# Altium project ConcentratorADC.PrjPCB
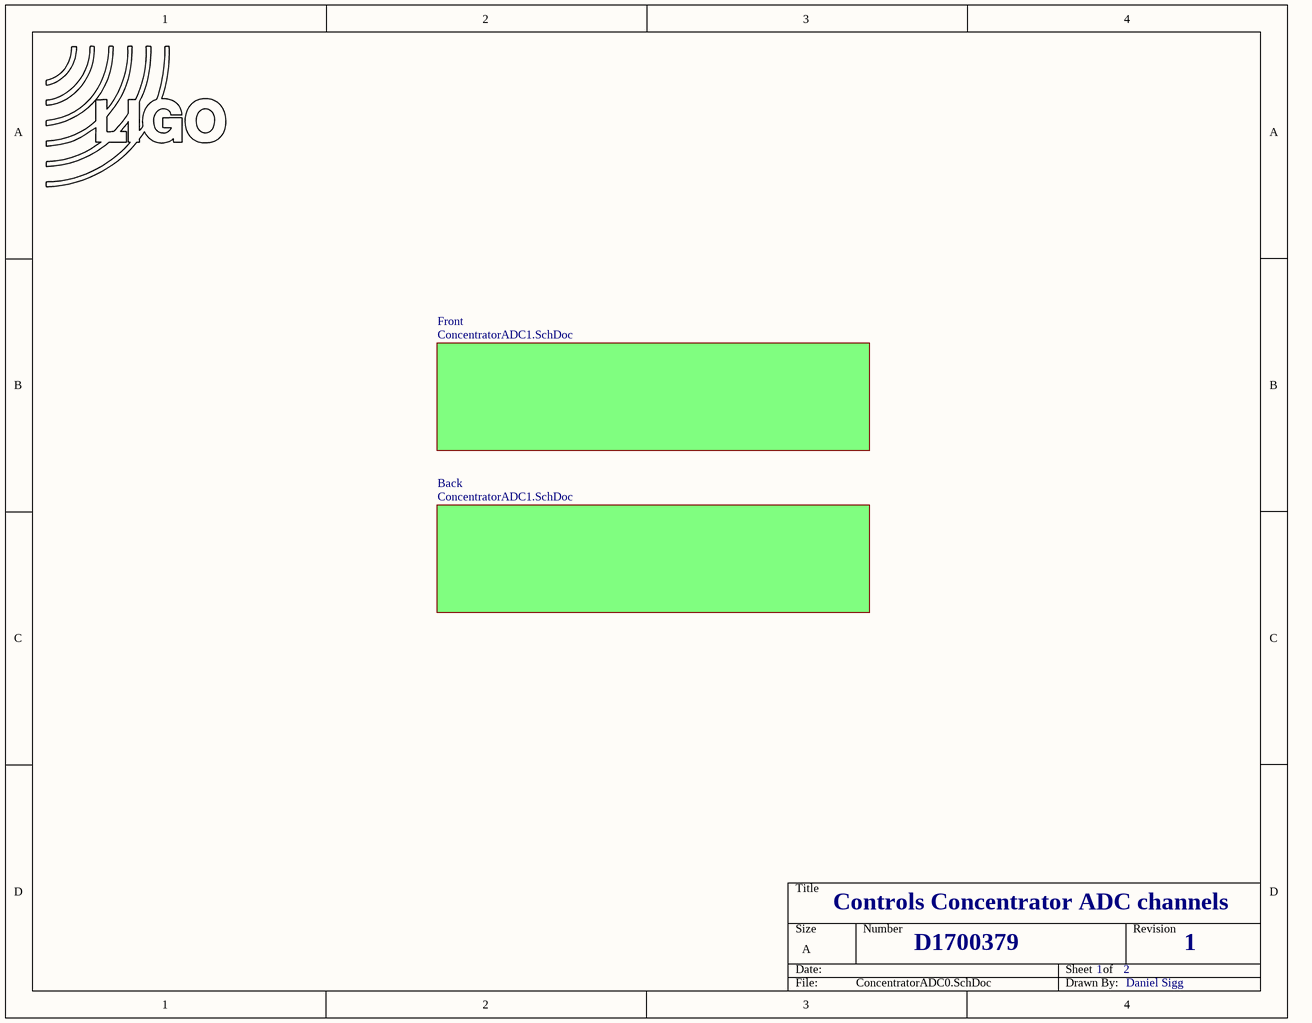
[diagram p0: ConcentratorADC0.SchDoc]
3 sheets, 115 parts. Net scope: flat (ports and power ports of the same name join across sheets).
Board file: ConcentratorADC.PcbDoc
Sheets:
  ConcentratorADC0.SchDoc
    Front = ConcentratorADC1.SchDoc
      OUT1 = ConcentratorADC2.SchDoc
      OUT2 = ConcentratorADC2.SchDoc
      OUT3 = ConcentratorADC2.SchDoc
      OUT4 = ConcentratorADC2.SchDoc
    Back = ConcentratorADC1.SchDoc
      OUT1 = ConcentratorADC2.SchDoc
      OUT2 = ConcentratorADC2.SchDoc
      OUT3 = ConcentratorADC2.SchDoc
      OUT4 = ConcentratorADC2.SchDoc

## Sheet ConcentratorADC0.SchDoc: D1700379
size A; Engineer: Daniel Sigg; Revision: 1; PageSetup: Record=PageOptions¦CenterHorizontal=True¦CenterVertical=True¦PrintScale=1.12¦XCorrection=1.00¦YCorrection=1.00¦PrintKind=0¦BorderSize=5000000¦LeftOffset=0¦BottomOffset=0¦Orientation=2¦PaperLength=1000¦PaperWidth=1000¦Scale=100¦PaperSource=7¦PrintQuality=-4¦MediaType=1¦DitherType=10¦PaperKind=Letter¦PrintScaleMode=1

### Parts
LOGO1  LIGO logo  [LIGO_LOGO]  (value not drawn)  (no BOM)

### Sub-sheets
Back = ConcentratorADC1.SchDoc: no entries
Front = ConcentratorADC1.SchDoc: no entries

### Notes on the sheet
- Controls Concentrator ADC channels
- D1700379
- 1
- 2
- Daniel Sigg

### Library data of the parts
LOGO1 = LIGO_logo

## Sheet ConcentratorADC1.SchDoc: D1700379
size A; Engineer: Daniel Sigg; Revision: 1; PageSetup: Record=PageOptions¦CenterHorizontal=True¦CenterVertical=True¦PrintScale=1.12¦XCorrection=1.00¦YCorrection=1.00¦PrintKind=0¦BorderSize=5000000¦LeftOffset=0¦BottomOffset=0¦Orientation=2¦PaperLength=1000¦PaperWidth=1000¦Scale=100¦PaperSource=7¦PrintQuality=-4¦MediaType=1¦DitherType=10¦PaperKind=Letter¦PrintScaleMode=1
Used 2 times, as channels Front, Back. Parts and nets are listed once, with the designators drawn on the sheet.
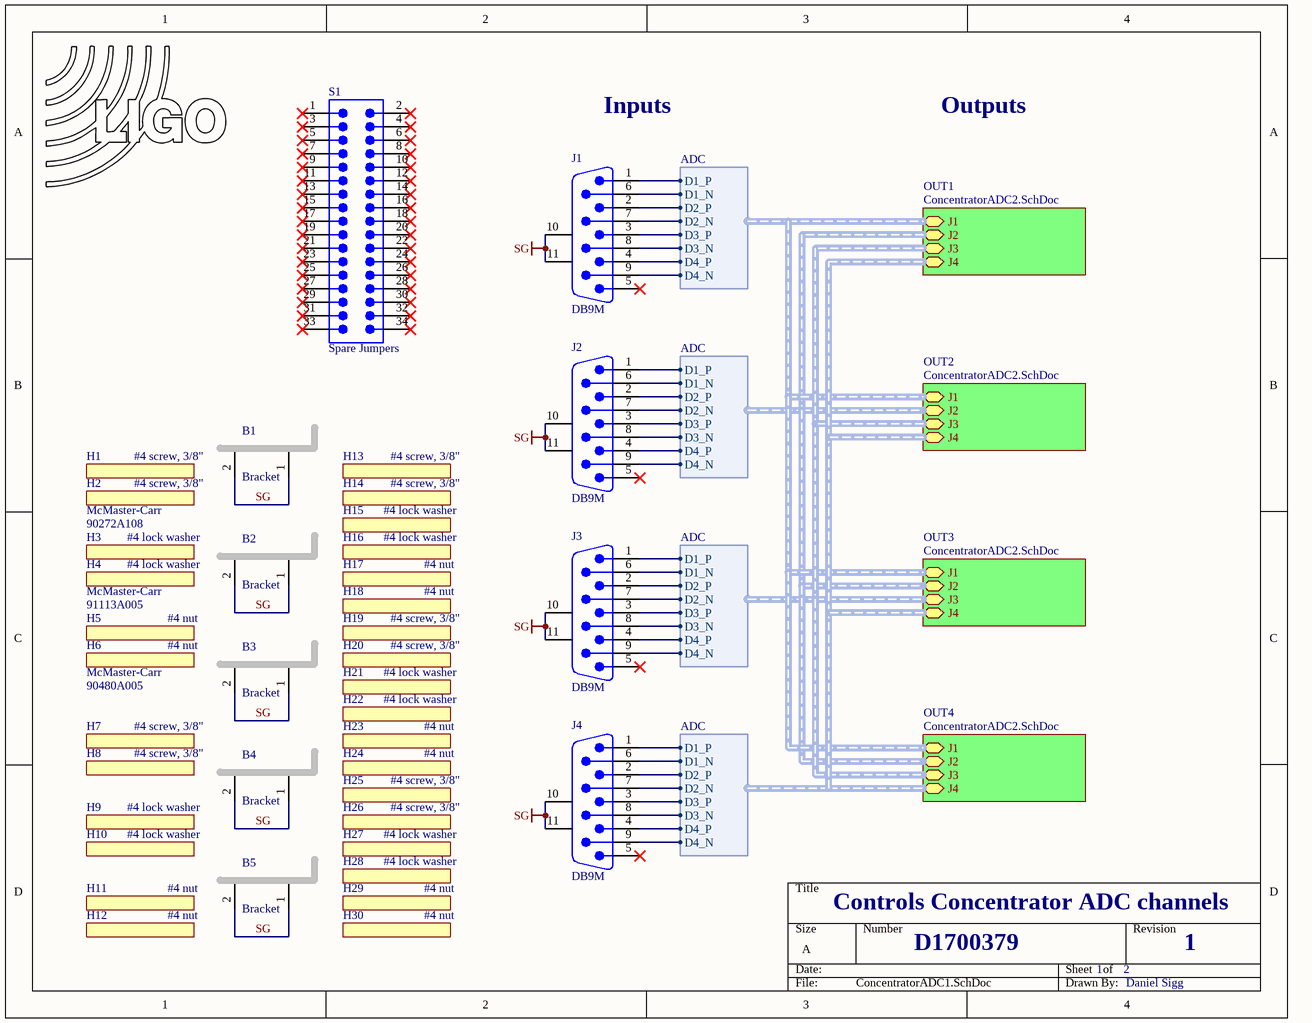
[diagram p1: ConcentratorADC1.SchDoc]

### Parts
B1  Bracket  [Bracket-RA_708]
B2  Bracket  [Bracket-RA_708]
B3  Bracket  [Bracket-RA_708]
B4  Bracket  [Bracket-RA_708]
B5  Bracket  [Bracket-RA_708]
H1  #4 screw, 3/8"  (mechanical)
H2  #4 screw, 3/8"  Part Number: 90272A108  Distributor: McMaster-Carr  (mechanical)
H3  #4 lock washer  (mechanical)
H4  #4 lock washer  Part Number: 91113A005  Distributor: McMaster-Carr  (mechanical)
H5  #4 nut  (mechanical)
H6  #4 nut  Part Number: 90480A005  Distributor: McMaster-Carr  (mechanical)
H7  #4 screw, 3/8"  (mechanical)
H8  #4 screw, 3/8"  (mechanical)
H9  #4 lock washer  (mechanical)
H10  #4 lock washer  (mechanical)
H11  #4 nut  (mechanical)
H12  #4 nut  (mechanical)
H13  #4 screw, 3/8"  (mechanical)
H14  #4 screw, 3/8"  (mechanical)
H15  #4 lock washer  (mechanical)
H16  #4 lock washer  (mechanical)
H17  #4 nut  (mechanical)
H18  #4 nut  (mechanical)
H19  #4 screw, 3/8"  (mechanical)
H20  #4 screw, 3/8"  (mechanical)
H21  #4 lock washer  (mechanical)
H22  #4 lock washer  (mechanical)
H23  #4 nut  (mechanical)
H24  #4 nut  (mechanical)
H25  #4 screw, 3/8"  (mechanical)
H26  #4 screw, 3/8"  (mechanical)
H27  #4 lock washer  (mechanical)
H28  #4 lock washer  (mechanical)
H29  #4 nut  (mechanical)
H30  #4 nut  (mechanical)
J1  DB9M  [DB9M-RA]
J2  DB9M  [DB9M-RA]
J3  DB9M  [DB9M-RA]
J4  DB9M  [DB9M-RA]
LOGO1  LIGO logo  [LIGO_LOGO]  (value not drawn)  (graphical)
S1  Spare Jumpers  [9181349421]

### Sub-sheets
OUT1 = ConcentratorADC2.SchDoc: J1 (harness ADC), J2 (harness ADC), J3 (harness ADC), J4 (harness ADC)
OUT2 = ConcentratorADC2.SchDoc: J1 (harness ADC), J2 (harness ADC), J3 (harness ADC), J4 (harness ADC)
OUT3 = ConcentratorADC2.SchDoc: J1 (harness ADC), J2 (harness ADC), J3 (harness ADC), J4 (harness ADC)
OUT4 = ConcentratorADC2.SchDoc: J1 (harness ADC), J2 (harness ADC), J3 (harness ADC), J4 (harness ADC)

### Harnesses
ADC: D1_P, D1_N, D2_P, D2_N, D3_P, D3_N, D4_P, D4_N

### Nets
SG: B1.1(GND) B1.2(GND) B2.1(GND) B2.2(GND) B3.1(GND) B3.2(GND) B4.1(GND) B4.2(GND) B5.1(GND) B5.2(GND) J1.10(MH1) J1.11(MH2) J2.10(MH1) J2.11(MH2) J3.10(MH1) J3.11(MH2) J4.10(MH1) J4.11(MH2)
NetJ1_1: J1.1 ; sheet OUT1/J1.D1_P
NetJ1_2: J1.2 ; sheet OUT1/J1.D2_P
NetJ1_3: J1.3 ; sheet OUT1/J1.D3_P
NetJ1_4: J1.4 ; sheet OUT1/J1.D4_P
NetJ1_6: J1.6 ; sheet OUT1/J1.D1_N
NetJ1_7: J1.7 ; sheet OUT1/J1.D2_N
NetJ1_8: J1.8 ; sheet OUT1/J1.D3_N
NetJ1_9: J1.9 ; sheet OUT1/J1.D4_N
NetJ2_1: J2.1 ; sheet OUT1/J2.D1_P
NetJ2_2: J2.2 ; sheet OUT1/J2.D2_P
NetJ2_3: J2.3 ; sheet OUT1/J2.D3_P
NetJ2_4: J2.4 ; sheet OUT1/J2.D4_P
NetJ2_6: J2.6 ; sheet OUT1/J2.D1_N
NetJ2_7: J2.7 ; sheet OUT1/J2.D2_N
NetJ2_8: J2.8 ; sheet OUT1/J2.D3_N
NetJ2_9: J2.9 ; sheet OUT1/J2.D4_N
NetJ3_1: J3.1 ; sheet OUT1/J3.D1_P
NetJ3_2: J3.2 ; sheet OUT1/J3.D2_P
NetJ3_3: J3.3 ; sheet OUT1/J3.D3_P
NetJ3_4: J3.4 ; sheet OUT1/J3.D4_P
NetJ3_6: J3.6 ; sheet OUT1/J3.D1_N
NetJ3_7: J3.7 ; sheet OUT1/J3.D2_N
NetJ3_8: J3.8 ; sheet OUT1/J3.D3_N
NetJ3_9: J3.9 ; sheet OUT1/J3.D4_N
NetJ4_1: J4.1 ; sheet OUT1/J4.D1_P
NetJ4_2: J4.2 ; sheet OUT1/J4.D2_P
NetJ4_3: J4.3 ; sheet OUT1/J4.D3_P
NetJ4_4: J4.4 ; sheet OUT1/J4.D4_P
NetJ4_6: J4.6 ; sheet OUT1/J4.D1_N
NetJ4_7: J4.7 ; sheet OUT1/J4.D2_N
NetJ4_8: J4.8 ; sheet OUT1/J4.D3_N
NetJ4_9: J4.9 ; sheet OUT1/J4.D4_N

Not connected (* = marked no-connect by the designer): J1 5*; J2 5*; J3 5*; J4 5*; S1 1* 2* 3* 4* 5* 6* 7* 8* 9* 10* 11* 12* 13* 14* 15* 16* 17* 18* 19* 20* 21* 22* 23* 24* 25* 26* 27* 28* 29* 30* 31* 32* 33* 34*

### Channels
Front: designators B1=B1B B2=B2B B3=B3B B4=B4B B5=B5B H1=H1A H2=H2A H3=H3A H4=H4A H5=H5A H6=H6A H7=H7A H8=H8A H9=H9A H10=H10A H11=H11A H12=H12A H13=H13A H14=H14A H15=H15A H16=H16A H17=H17A H18=H18A H19=H19A H20=H20A H21=H21A H22=H22A H23=H23A H24=H24A H25=H25A H26=H26A H27=H27A H28=H28A H29=H29A H30=H30A J1=J1B J2=J2B J3=J3B J4=J4B LOGO1=LOGO1A S1=S1B
Back: designators B1=B1A B2=B2A B3=B3A B4=B4A B5=B5A H1=H1B H2=H2B H3=H3B H4=H4B H5=H5B H6=H6B H7=H7B H8=H8B H9=H9B H10=H10B H11=H11B H12=H12B H13=H13B H14=H14B H15=H15B H16=H16B H17=H17B H18=H18B H19=H19B H20=H20B H21=H21B H22=H22B H23=H23B H24=H24B H25=H25B H26=H26B H27=H27B H28=H28B H29=H29B H30=H30B J1=J1A J2=J2A J3=J3A J4=J4A LOGO1=LOGO1B S1=S1A

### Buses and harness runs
harness sheet OUT1/J1 = sheet OUT2/J1 = sheet OUT3/J1 = sheet OUT4/J1
harness sheet OUT1/J2 = sheet OUT2/J2 = sheet OUT3/J2 = sheet OUT4/J2
harness sheet OUT1/J3 = sheet OUT2/J3 = sheet OUT3/J3 = sheet OUT4/J3
harness sheet OUT1/J4 = sheet OUT2/J4 = sheet OUT3/J4 = sheet OUT4/J4

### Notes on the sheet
- Inputs
- Outputs
- Controls Concentrator ADC channels
- D1700379
- 1
- 2
- Daniel Sigg

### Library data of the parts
B1-B5 = Bracket_708: Keystone Electronics right-angle 6-32 steel, 708; Part Number: 708K-ND
H1 H7 H8 H13 H14 H19 H20 H25 H26 = Partlist: Mounting hardware; Part Number: 90272A108
H2 H4 H6 = Partlist: Mounting hardware
H3 H9 H10 H15 H16 H21 H22 H27 H28 = Partlist: Mounting hardware; Part Number: 91113A005
H5 H11 H12 H17 H18 H23 H24 H29 H30 = Partlist: Mounting hardware; Part Number: 90480A005
J1-J4 = DB9M: Plug Assembly, 9 Position, Right Angle, .318 Series; Part Number: A32094-ND
LOGO1 = LIGO_logo
S1 = 09 18 134 9421: Flat Cable Connector (IDC), PCB Transition Connector, 2 Rows, Kinked Solder Pin, 34 Contacts; Part Number: 609-3208-ND

## Sheet ConcentratorADC2.SchDoc
size A
Used 8 times, as channels Front/OUT1, Front/OUT2, Front/OUT3, Front/OUT4, Back/OUT1, Back/OUT2, Back/OUT3, Back/OUT4. Parts and nets are listed once, with the designators drawn on the sheet.
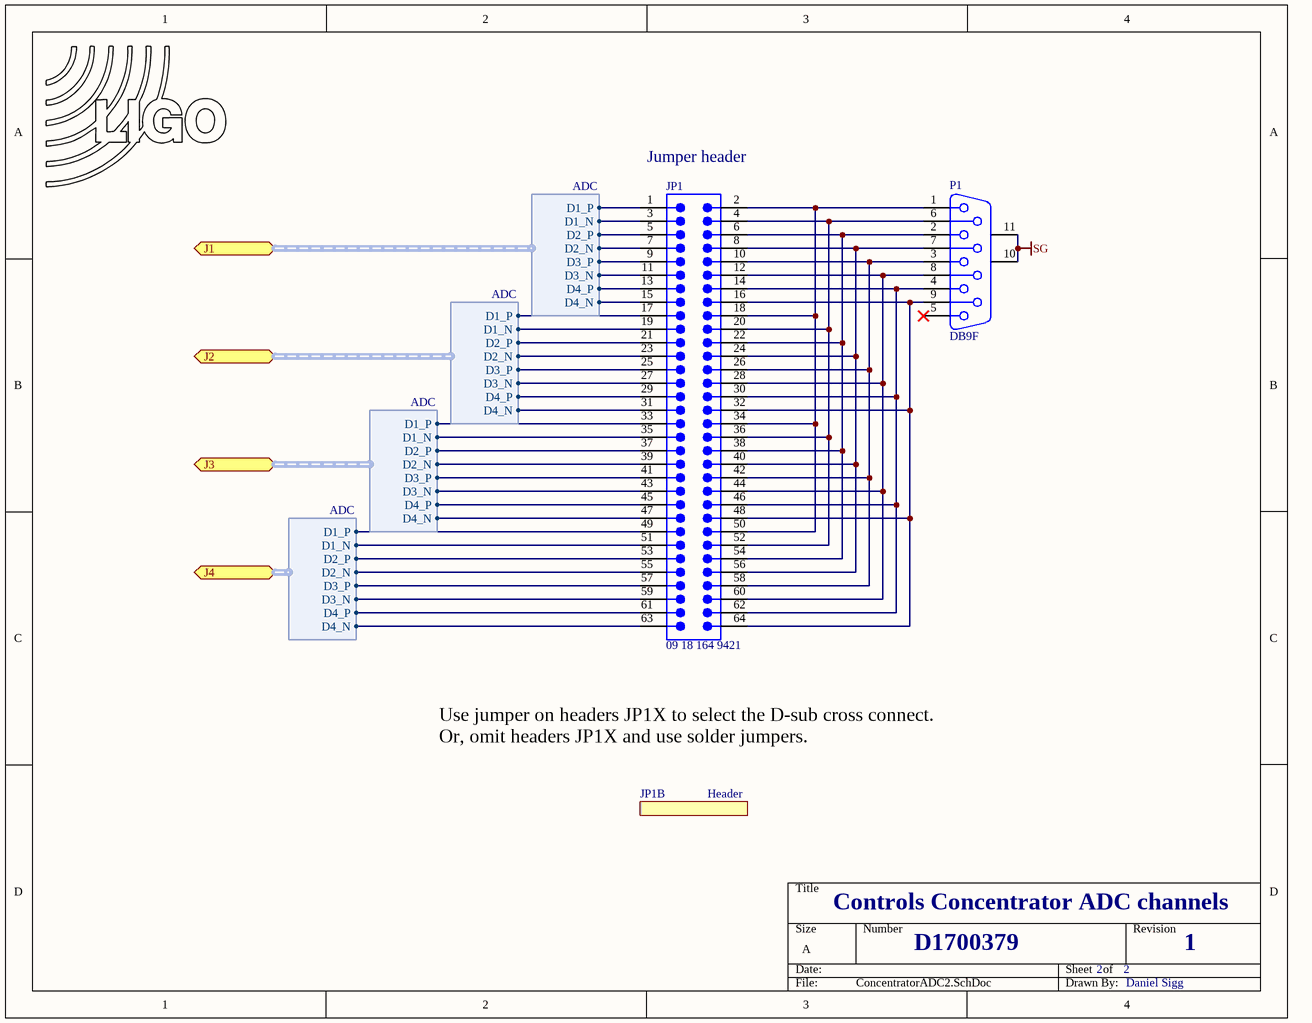
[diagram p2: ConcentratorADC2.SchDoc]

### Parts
JP1  09 18 164 9421  [9181649421]
JP1B  Header  (mechanical)
LOGO?  LIGO logo  [LIGO_LOGO]  (value not drawn)  (graphical)
P1  DB9F  [DB9F-RA]

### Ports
J1 (harness ADC), J2 (harness ADC), J3 (harness ADC), J4 (harness ADC)

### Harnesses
ADC: D1_P, D1_N, D2_P, D2_N, D3_P, D3_N, D4_P, D4_N

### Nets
SG: P1.10(MH1) P1.11(MH2)
NetJP1_1: JP1.1 ; port J1.D1_P
NetJP1_2: JP1.2 JP1.18 JP1.34 JP1.50 P1.1
NetJP1_3: JP1.3 ; port J1.D1_N
NetJP1_4: JP1.4 JP1.20 JP1.36 JP1.52 P1.6
NetJP1_5: JP1.5 ; port J1.D2_P
NetJP1_6: JP1.6 JP1.22 JP1.38 JP1.54 P1.2
NetJP1_7: JP1.7 ; port J1.D2_N
NetJP1_8: JP1.8 JP1.24 JP1.40 JP1.56 P1.7
NetJP1_9: JP1.9 ; port J1.D3_P
NetJP1_10: JP1.10 JP1.26 JP1.42 JP1.58 P1.3
NetJP1_11: JP1.11 ; port J1.D3_N
NetJP1_12: JP1.12 JP1.28 JP1.44 JP1.60 P1.8
NetJP1_13: JP1.13 ; port J1.D4_P
NetJP1_14: JP1.14 JP1.30 JP1.46 JP1.62 P1.4
NetJP1_15: JP1.15 ; port J1.D4_N
NetJP1_16: JP1.16 JP1.32 JP1.48 JP1.64 P1.9
NetJP1_17: JP1.17 ; port J2.D1_P
NetJP1_19: JP1.19 ; port J2.D1_N
NetJP1_21: JP1.21 ; port J2.D2_P
NetJP1_23: JP1.23 ; port J2.D2_N
NetJP1_25: JP1.25 ; port J2.D3_P
NetJP1_27: JP1.27 ; port J2.D3_N
NetJP1_29: JP1.29 ; port J2.D4_P
NetJP1_31: JP1.31 ; port J2.D4_N
NetJP1_33: JP1.33 ; port J3.D1_P
NetJP1_35: JP1.35 ; port J3.D1_N
NetJP1_37: JP1.37 ; port J3.D2_P
NetJP1_39: JP1.39 ; port J3.D2_N
NetJP1_41: JP1.41 ; port J3.D3_P
NetJP1_43: JP1.43 ; port J3.D3_N
NetJP1_45: JP1.45 ; port J3.D4_P
NetJP1_47: JP1.47 ; port J3.D4_N
NetJP1_49: JP1.49 ; port J4.D1_P
NetJP1_51: JP1.51 ; port J4.D1_N
NetJP1_53: JP1.53 ; port J4.D2_P
NetJP1_55: JP1.55 ; port J4.D2_N
NetJP1_57: JP1.57 ; port J4.D3_P
NetJP1_59: JP1.59 ; port J4.D3_N
NetJP1_61: JP1.61 ; port J4.D4_P
NetJP1_63: JP1.63 ; port J4.D4_N

Not connected (* = marked no-connect by the designer): P1 5*

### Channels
Front/OUT1: designators JP1=JP1E JP1B=JP1BA LOGO?=LOGO?A P1=P1E
Front/OUT2: designators JP1=JP1F JP1B=JP1BB LOGO?=LOGO?B P1=P1F
Front/OUT3: designators JP1=JP1G JP1B=JP1BC LOGO?=LOGO?C P1=P1G
Front/OUT4: designators JP1=JP1H JP1B=JP1BD LOGO?=LOGO?D P1=P1H
Back/OUT1: designators JP1=JP1A JP1B=JP1BE LOGO?=LOGO?E P1=P1A
Back/OUT2: designators JP1=JP1B JP1B=JP1BF LOGO?=LOGO?F P1=P1B
Back/OUT3: designators JP1=JP1C JP1B=JP1BG LOGO?=LOGO?G P1=P1C
Back/OUT4: designators JP1=JP1D JP1B=JP1BH LOGO?=LOGO?H P1=P1D

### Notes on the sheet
- (near JP1) Jumper header
- Use jumper on headers JP1X to select the D-sub cross connect.
  Or, omit headers JP1X and use solder jumpers.
- Controls Concentrator ADC channels
- D1700379
- 2
- 1
- Daniel Sigg

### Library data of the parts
JP1 = 09 18 164 9421: Flat Cable Connector (IDC), PCB Transition Connector, 2 Rows, Kinked Solder Pin, 64 Contacts; Part Number: 609-3208-ND
JP1B = Partlist: Mounting hardware; Part Number: 609-3208-ND
LOGO? = LIGO_logo
P1 = DB9F: Receptacle Assembly, 9 Position, Right Angle, .318 Series; Part Number: A32119-ND

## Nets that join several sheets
SG: Front (18 pins), Front/OUT1 (P1E.10 P1E.11), Front/OUT2 (P1F.10 P1F.11), Front/OUT3 (P1G.10 P1G.11), Front/OUT4 (P1H.10 P1H.11), Back (18 pins), Back/OUT1 (P1A.10 P1A.11), Back/OUT2 (P1B.10 P1B.11), Back/OUT3 (P1C.10 P1C.11), Back/OUT4 (P1D.10 P1D.11)
NetJP1A_1: Front/OUT1 (JP1E.1), Front/OUT2 (JP1F.1), Front/OUT3 (JP1G.1), Front/OUT4 (JP1H.1), Back/OUT1 (JP1A.1), Back/OUT2 (JP1B.1), Back/OUT3 (JP1C.1), Back/OUT4 (JP1D.1)
NetJP1A_3: Front/OUT1 (JP1E.3), Front/OUT2 (JP1F.3), Front/OUT3 (JP1G.3), Front/OUT4 (JP1H.3), Back/OUT1 (JP1A.3), Back/OUT2 (JP1B.3), Back/OUT3 (JP1C.3), Back/OUT4 (JP1D.3)
NetJP1A_5: Front/OUT1 (JP1E.5), Front/OUT2 (JP1F.5), Front/OUT3 (JP1G.5), Front/OUT4 (JP1H.5), Back/OUT1 (JP1A.5), Back/OUT2 (JP1B.5), Back/OUT3 (JP1C.5), Back/OUT4 (JP1D.5)
NetJP1A_7: Front/OUT1 (JP1E.7), Front/OUT2 (JP1F.7), Front/OUT3 (JP1G.7), Front/OUT4 (JP1H.7), Back/OUT1 (JP1A.7), Back/OUT2 (JP1B.7), Back/OUT3 (JP1C.7), Back/OUT4 (JP1D.7)
NetJP1A_9: Front/OUT1 (JP1E.9), Front/OUT2 (JP1F.9), Front/OUT3 (JP1G.9), Front/OUT4 (JP1H.9), Back/OUT1 (JP1A.9), Back/OUT2 (JP1B.9), Back/OUT3 (JP1C.9), Back/OUT4 (JP1D.9)
NetJP1A_11: Front/OUT1 (JP1E.11), Front/OUT2 (JP1F.11), Front/OUT3 (JP1G.11), Front/OUT4 (JP1H.11), Back/OUT1 (JP1A.11), Back/OUT2 (JP1B.11), Back/OUT3 (JP1C.11), Back/OUT4 (JP1D.11)
NetJP1A_13: Front/OUT1 (JP1E.13), Front/OUT2 (JP1F.13), Front/OUT3 (JP1G.13), Front/OUT4 (JP1H.13), Back/OUT1 (JP1A.13), Back/OUT2 (JP1B.13), Back/OUT3 (JP1C.13), Back/OUT4 (JP1D.13)
NetJP1A_15: Front/OUT1 (JP1E.15), Front/OUT2 (JP1F.15), Front/OUT3 (JP1G.15), Front/OUT4 (JP1H.15), Back/OUT1 (JP1A.15), Back/OUT2 (JP1B.15), Back/OUT3 (JP1C.15), Back/OUT4 (JP1D.15)
NetJP1A_17: Front/OUT1 (JP1E.17), Front/OUT2 (JP1F.17), Front/OUT3 (JP1G.17), Front/OUT4 (JP1H.17), Back/OUT1 (JP1A.17), Back/OUT2 (JP1B.17), Back/OUT3 (JP1C.17), Back/OUT4 (JP1D.17)
NetJP1A_19: Front/OUT1 (JP1E.19), Front/OUT2 (JP1F.19), Front/OUT3 (JP1G.19), Front/OUT4 (JP1H.19), Back/OUT1 (JP1A.19), Back/OUT2 (JP1B.19), Back/OUT3 (JP1C.19), Back/OUT4 (JP1D.19)
NetJP1A_21: Front/OUT1 (JP1E.21), Front/OUT2 (JP1F.21), Front/OUT3 (JP1G.21), Front/OUT4 (JP1H.21), Back/OUT1 (JP1A.21), Back/OUT2 (JP1B.21), Back/OUT3 (JP1C.21), Back/OUT4 (JP1D.21)
NetJP1A_23: Front/OUT1 (JP1E.23), Front/OUT2 (JP1F.23), Front/OUT3 (JP1G.23), Front/OUT4 (JP1H.23), Back/OUT1 (JP1A.23), Back/OUT2 (JP1B.23), Back/OUT3 (JP1C.23), Back/OUT4 (JP1D.23)
NetJP1A_25: Front/OUT1 (JP1E.25), Front/OUT2 (JP1F.25), Front/OUT3 (JP1G.25), Front/OUT4 (JP1H.25), Back/OUT1 (JP1A.25), Back/OUT2 (JP1B.25), Back/OUT3 (JP1C.25), Back/OUT4 (JP1D.25)
NetJP1A_27: Front/OUT1 (JP1E.27), Front/OUT2 (JP1F.27), Front/OUT3 (JP1G.27), Front/OUT4 (JP1H.27), Back/OUT1 (JP1A.27), Back/OUT2 (JP1B.27), Back/OUT3 (JP1C.27), Back/OUT4 (JP1D.27)
NetJP1A_29: Front/OUT1 (JP1E.29), Front/OUT2 (JP1F.29), Front/OUT3 (JP1G.29), Front/OUT4 (JP1H.29), Back/OUT1 (JP1A.29), Back/OUT2 (JP1B.29), Back/OUT3 (JP1C.29), Back/OUT4 (JP1D.29)
NetJP1A_31: Front/OUT1 (JP1E.31), Front/OUT2 (JP1F.31), Front/OUT3 (JP1G.31), Front/OUT4 (JP1H.31), Back/OUT1 (JP1A.31), Back/OUT2 (JP1B.31), Back/OUT3 (JP1C.31), Back/OUT4 (JP1D.31)
NetJP1A_33: Front/OUT1 (JP1E.33), Front/OUT2 (JP1F.33), Front/OUT3 (JP1G.33), Front/OUT4 (JP1H.33), Back/OUT1 (JP1A.33), Back/OUT2 (JP1B.33), Back/OUT3 (JP1C.33), Back/OUT4 (JP1D.33)
NetJP1A_35: Front/OUT1 (JP1E.35), Front/OUT2 (JP1F.35), Front/OUT3 (JP1G.35), Front/OUT4 (JP1H.35), Back/OUT1 (JP1A.35), Back/OUT2 (JP1B.35), Back/OUT3 (JP1C.35), Back/OUT4 (JP1D.35)
NetJP1A_37: Front/OUT1 (JP1E.37), Front/OUT2 (JP1F.37), Front/OUT3 (JP1G.37), Front/OUT4 (JP1H.37), Back/OUT1 (JP1A.37), Back/OUT2 (JP1B.37), Back/OUT3 (JP1C.37), Back/OUT4 (JP1D.37)
NetJP1A_39: Front/OUT1 (JP1E.39), Front/OUT2 (JP1F.39), Front/OUT3 (JP1G.39), Front/OUT4 (JP1H.39), Back/OUT1 (JP1A.39), Back/OUT2 (JP1B.39), Back/OUT3 (JP1C.39), Back/OUT4 (JP1D.39)
NetJP1A_41: Front/OUT1 (JP1E.41), Front/OUT2 (JP1F.41), Front/OUT3 (JP1G.41), Front/OUT4 (JP1H.41), Back/OUT1 (JP1A.41), Back/OUT2 (JP1B.41), Back/OUT3 (JP1C.41), Back/OUT4 (JP1D.41)
NetJP1A_43: Front/OUT1 (JP1E.43), Front/OUT2 (JP1F.43), Front/OUT3 (JP1G.43), Front/OUT4 (JP1H.43), Back/OUT1 (JP1A.43), Back/OUT2 (JP1B.43), Back/OUT3 (JP1C.43), Back/OUT4 (JP1D.43)
NetJP1A_45: Front/OUT1 (JP1E.45), Front/OUT2 (JP1F.45), Front/OUT3 (JP1G.45), Front/OUT4 (JP1H.45), Back/OUT1 (JP1A.45), Back/OUT2 (JP1B.45), Back/OUT3 (JP1C.45), Back/OUT4 (JP1D.45)
NetJP1A_47: Front/OUT1 (JP1E.47), Front/OUT2 (JP1F.47), Front/OUT3 (JP1G.47), Front/OUT4 (JP1H.47), Back/OUT1 (JP1A.47), Back/OUT2 (JP1B.47), Back/OUT3 (JP1C.47), Back/OUT4 (JP1D.47)
NetJP1A_49: Front/OUT1 (JP1E.49), Front/OUT2 (JP1F.49), Front/OUT3 (JP1G.49), Front/OUT4 (JP1H.49), Back/OUT1 (JP1A.49), Back/OUT2 (JP1B.49), Back/OUT3 (JP1C.49), Back/OUT4 (JP1D.49)
NetJP1A_51: Front/OUT1 (JP1E.51), Front/OUT2 (JP1F.51), Front/OUT3 (JP1G.51), Front/OUT4 (JP1H.51), Back/OUT1 (JP1A.51), Back/OUT2 (JP1B.51), Back/OUT3 (JP1C.51), Back/OUT4 (JP1D.51)
NetJP1A_53: Front/OUT1 (JP1E.53), Front/OUT2 (JP1F.53), Front/OUT3 (JP1G.53), Front/OUT4 (JP1H.53), Back/OUT1 (JP1A.53), Back/OUT2 (JP1B.53), Back/OUT3 (JP1C.53), Back/OUT4 (JP1D.53)
NetJP1A_55: Front/OUT1 (JP1E.55), Front/OUT2 (JP1F.55), Front/OUT3 (JP1G.55), Front/OUT4 (JP1H.55), Back/OUT1 (JP1A.55), Back/OUT2 (JP1B.55), Back/OUT3 (JP1C.55), Back/OUT4 (JP1D.55)
NetJP1A_57: Front/OUT1 (JP1E.57), Front/OUT2 (JP1F.57), Front/OUT3 (JP1G.57), Front/OUT4 (JP1H.57), Back/OUT1 (JP1A.57), Back/OUT2 (JP1B.57), Back/OUT3 (JP1C.57), Back/OUT4 (JP1D.57)
NetJP1A_59: Front/OUT1 (JP1E.59), Front/OUT2 (JP1F.59), Front/OUT3 (JP1G.59), Front/OUT4 (JP1H.59), Back/OUT1 (JP1A.59), Back/OUT2 (JP1B.59), Back/OUT3 (JP1C.59), Back/OUT4 (JP1D.59)
NetJP1A_61: Front/OUT1 (JP1E.61), Front/OUT2 (JP1F.61), Front/OUT3 (JP1G.61), Front/OUT4 (JP1H.61), Back/OUT1 (JP1A.61), Back/OUT2 (JP1B.61), Back/OUT3 (JP1C.61), Back/OUT4 (JP1D.61)
NetJP1A_63: Front/OUT1 (JP1E.63), Front/OUT2 (JP1F.63), Front/OUT3 (JP1G.63), Front/OUT4 (JP1H.63), Back/OUT1 (JP1A.63), Back/OUT2 (JP1B.63), Back/OUT3 (JP1C.63), Back/OUT4 (JP1D.63)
